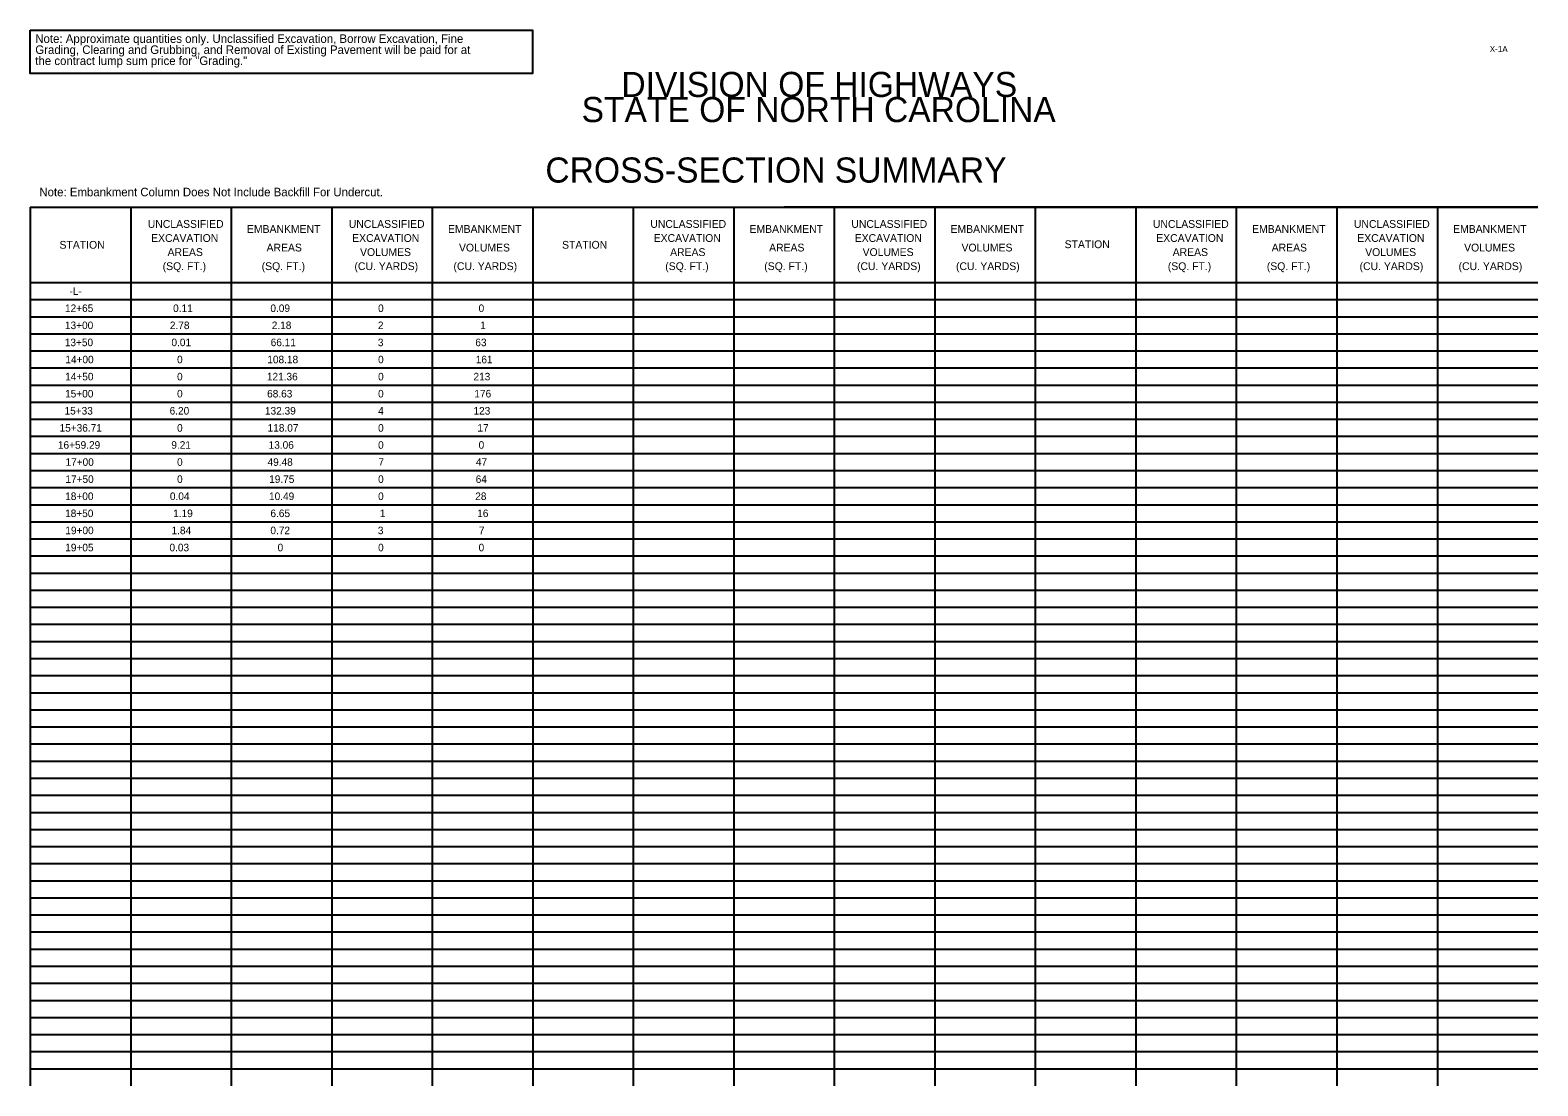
# Model space of a CAD drawing. Extents: x 2473106 to 2475402, y 633617 to 633851.
# Drawn here: x 2473105.7 to 2473405.7, y 633617.5 to 633827.5 of the extents above; entities that cross this region are included whole.
import ezdxf

# ---------------------------------------------------------------- set-up
doc = ezdxf.new("R2010")
doc.units = 0
for name, color, linetype in [('Prop CMT Shld Paved Course 2', 7, 'Continuous'), ('Prop CMT Subgrade Earthwork', 7, 'Continuous'), ('Prop XS SE Text', 7, 'Continuous')]:
    doc.layers.add(name, color=color, linetype=linetype)

msp = doc.modelspace()

# ---------------------------------------------------------------- linework, layer by layer
at = {"layer": 'Prop CMT Subgrade Earthwork'}
msp.add_lwpolyline([(2473105.69, 633827.47), (2473205.67, 633827.47), (2473205.67, 633818.82), (2473105.69, 633818.82)], close=True, dxfattribs=at)
at = {"layer": 'Prop XS SE Text'}
for p, q in [((2473105.69, 633792.27), (2473405.69, 633792.37)), ((2473105.69, 633792.27), (2473405.69, 633792.27)), ((2473105.69, 633792.27), (2473105.69, 633617.47)), ((2473125.69, 633792.27), (2473125.69, 633617.47)), ((2473145.69, 633792.27), (2473145.69, 633617.47)), ((2473165.69, 633792.27), (2473165.69, 633617.47)), ((2473185.69, 633792.27), (2473185.69, 633617.47)), ((2473205.69, 633792.27), (2473205.69, 633617.47)), ((2473225.69, 633792.27), (2473225.69, 633617.47)), ((2473245.69, 633792.27), (2473245.69, 633617.47)), ((2473265.69, 633792.27), (2473265.69, 633617.47)), ((2473285.69, 633792.27), (2473285.69, 633617.47)), ((2473305.69, 633792.27), (2473305.69, 633617.47)), ((2473325.69, 633792.27), (2473325.69, 633617.47)), ((2473345.69, 633792.27), (2473345.69, 633617.47)), ((2473365.69, 633792.27), (2473365.69, 633617.47)), ((2473385.69, 633792.27), (2473385.69, 633617.47)), ((2473105.69, 633777.27), (2473405.69, 633777.27)), ((2473105.69, 633773.87), (2473405.69, 633773.87)), ((2473105.69, 633770.47), (2473405.69, 633770.47)), ((2473105.69, 633767.07), (2473405.69, 633767.07)), ((2473105.69, 633763.67), (2473405.69, 633763.67)), ((2473105.69, 633760.27), (2473405.69, 633760.27)), ((2473105.69, 633756.87), (2473405.69, 633756.87)), ((2473105.69, 633753.47), (2473405.69, 633753.47)), ((2473105.69, 633750.07), (2473405.69, 633750.07)), ((2473105.69, 633746.67), (2473405.69, 633746.67)), ((2473105.69, 633743.27), (2473405.69, 633743.27)), ((2473105.69, 633739.87), (2473405.69, 633739.87)), ((2473105.69, 633736.47), (2473405.69, 633736.47)), ((2473105.69, 633736.47), (2473405.69, 633736.47)), ((2473105.69, 633733.07), (2473405.69, 633733.07)), ((2473105.69, 633729.67), (2473405.69, 633729.67)), ((2473105.69, 633726.27), (2473405.69, 633726.27)), ((2473105.69, 633722.87), (2473405.69, 633722.87)), ((2473105.69, 633719.47), (2473405.69, 633719.47)), ((2473105.69, 633716.07), (2473405.69, 633716.07)), ((2473105.69, 633712.67), (2473405.69, 633712.67)), ((2473105.69, 633709.27), (2473405.69, 633709.27)), ((2473105.69, 633705.87), (2473405.69, 633705.87)), ((2473105.69, 633702.47), (2473405.69, 633702.47)), ((2473105.69, 633699.07), (2473405.69, 633699.07)), ((2473105.69, 633695.67), (2473405.69, 633695.67)), ((2473105.69, 633692.27), (2473405.69, 633692.27)), ((2473105.69, 633688.87), (2473405.69, 633688.87)), ((2473105.69, 633685.47), (2473405.69, 633685.47)), ((2473105.69, 633682.07), (2473405.69, 633682.07)), ((2473105.69, 633678.67), (2473405.69, 633678.67)), ((2473105.69, 633675.27), (2473405.69, 633675.27)), ((2473105.69, 633671.87), (2473405.69, 633671.87)), ((2473105.69, 633668.47), (2473405.69, 633668.47)), ((2473105.69, 633665.07), (2473405.69, 633665.07)), ((2473105.69, 633661.67), (2473405.69, 633661.67)), ((2473105.69, 633658.27), (2473405.69, 633658.27)), ((2473105.69, 633654.87), (2473405.69, 633654.87)), ((2473105.69, 633651.47), (2473405.69, 633651.47)), ((2473105.69, 633648.07), (2473405.69, 633648.07)), ((2473105.69, 633644.67), (2473405.69, 633644.67)), ((2473105.69, 633641.27), (2473405.69, 633641.27)), ((2473105.69, 633637.87), (2473405.69, 633637.87)), ((2473105.69, 633634.47), (2473405.69, 633634.47)), ((2473105.69, 633631.07), (2473405.69, 633631.07)), ((2473105.69, 633627.67), (2473405.69, 633627.67)), ((2473105.69, 633624.27), (2473405.69, 633624.27)), ((2473105.69, 633620.87), (2473405.69, 633620.87))]:
    msp.add_line(p, q, dxfattribs=at)

# ---------------------------------------------------------------- texts
at = {"layer": 'Prop CMT Shld Paved Course 2'}
for s, p in [('Note: Approximate quantities only. Unclassified Excavation, Borrow Excavation, Fine ', (2473106.71, 633824.93)), ('the contract lump sum price for "Grading."', (2473106.71, 633820.53)), ('Grading, Clearing and Grubbing, and Removal of Existing Pavement will be paid for at', (2473106.71, 633822.73))]:
    msp.add_text(s, height=1.7, dxfattribs=at).set_placement(p)
msp.add_text('Note: Embankment Column Does Not Include Backfill For Undercut.', height=1.7, rotation=360, dxfattribs=at).set_placement((2473107.52, 633794.42))
at = {"layer": 'Prop XS SE Text'}
for s, height, p in [('X-1A', 1.2, (2473396.12, 633823.11)), ('CROSS-SECTION SUMMARY', 5, (2473208.21, 633797.14)), ('UNCLASSIFIED', 1.55, (2473129.09, 633788.14)), ('UNCLASSIFIED', 1.55, (2473169.09, 633788.14)), ('UNCLASSIFIED', 1.55, (2473229.09, 633788.14)), ('UNCLASSIFIED', 1.55, (2473269.09, 633788.14)), ('UNCLASSIFIED', 1.55, (2473329.09, 633788.14)), ('UNCLASSIFIED', 1.55, (2473369.09, 633788.14)), ('EXCAVATION', 1.55, (2473129.76, 633785.34)), ('EMBANKMENT', 1.55, (2473148.83, 633787.14)), ('EXCAVATION', 1.55, (2473169.76, 633785.34)), ('EMBANKMENT', 1.55, (2473188.83, 633787.14)), ('EXCAVATION', 1.55, (2473229.76, 633785.34)), ('EMBANKMENT', 1.55, (2473248.83, 633787.14)), ('EXCAVATION', 1.55, (2473269.76, 633785.34)), ('EMBANKMENT', 1.55, (2473288.83, 633787.14)), ('EXCAVATION', 1.55, (2473329.76, 633785.34)), ('EMBANKMENT', 1.55, (2473348.83, 633787.14)), ('EXCAVATION', 1.55, (2473369.76, 633785.34)), ('EMBANKMENT', 1.55, (2473388.83, 633787.14)), ('STATION', 1.55, (2473111.53, 633783.99)), ('AREAS', 1.55, (2473133.03, 633782.54)), ('AREAS', 1.55, (2473152.73, 633783.44)), ('VOLUMES', 1.55, (2473171.33, 633782.54)), ('VOLUMES', 1.55, (2473191.02, 633783.44)), ('STATION', 1.55, (2473211.53, 633783.99)), ('AREAS', 1.55, (2473233.03, 633782.54)), ('AREAS', 1.55, (2473252.73, 633783.44)), ('VOLUMES', 1.55, (2473271.33, 633782.54)), ('VOLUMES', 1.55, (2473291.02, 633783.44)), ('STATION', 1.55, (2473311.53, 633784.1)), ('AREAS', 1.55, (2473333.03, 633782.54)), ('AREAS', 1.55, (2473352.73, 633783.44)), ('VOLUMES', 1.55, (2473371.33, 633782.54)), ('VOLUMES', 1.55, (2473391.02, 633783.44)), ('(SQ. FT.)', 1.55, (2473132.06, 633779.74)), ('(SQ. FT.)', 1.55, (2473151.76, 633779.74)), ('(CU. YARDS)', 1.55, (2473170.22, 633779.74)), ('(CU. YARDS)', 1.55, (2473189.92, 633779.74)), ('(SQ. FT.)', 1.55, (2473232.06, 633779.74)), ('(SQ. FT.)', 1.55, (2473251.76, 633779.74)), ('(CU. YARDS)', 1.55, (2473270.22, 633779.74)), ('(CU. YARDS)', 1.55, (2473289.92, 633779.74)), ('(SQ. FT.)', 1.55, (2473332.06, 633779.74)), ('(SQ. FT.)', 1.55, (2473351.76, 633779.74)), ('(CU. YARDS)', 1.55, (2473370.22, 633779.74)), ('(CU. YARDS)', 1.55, (2473389.92, 633779.74)), ('-L-', 1.5, (2473113.5, 633774.8)), ('12+65', 1.5, (2473112.62, 633771.4)), ('0.11', 1.5, (2473134.13, 633771.4)), ('0.09', 1.5, (2473153.49, 633771.4)), ('0', 1.5, (2473174.92, 633771.4)), ('0', 1.5, (2473194.92, 633771.4)), ('13+00', 1.5, (2473112.61, 633768)), ('2.78', 1.5, (2473133.49, 633768)), ('2.18', 1.5, (2473153.76, 633768)), ('2', 1.5, (2473174.88, 633768)), ('1', 1.5, (2473195.25, 633768)), ('13+50', 1.5, (2473112.58, 633764.6)), ('0.01', 1.5, (2473133.8, 633764.6)), ('66.11', 1.5, (2473153.55, 633764.6)), ('3', 1.5, (2473174.87, 633764.6)), ('63', 1.5, (2473194.27, 633764.6)), ('14+00', 1.5, (2473112.69, 633761.2)), ('0', 1.5, (2473134.92, 633761.2)), ('108.18', 1.5, (2473152.88, 633761.2)), ('0', 1.5, (2473174.92, 633761.2)), ('161', 1.5, (2473194.35, 633761.2)), ('14+50', 1.5, (2473112.66, 633757.8)), ('0', 1.5, (2473134.92, 633757.8)), ('121.36', 1.5, (2473152.79, 633757.8)), ('0', 1.5, (2473174.92, 633757.8)), ('213', 1.5, (2473193.9, 633757.8)), ('15+00', 1.5, (2473112.64, 633754.4)), ('0', 1.5, (2473134.92, 633754.4)), ('68.63', 1.5, (2473152.84, 633754.4)), ('0', 1.5, (2473174.92, 633754.4)), ('176', 1.5, (2473194.08, 633754.4)), ('15+33', 1.5, (2473112.53, 633751)), ('6.20', 1.5, (2473133.44, 633751)), ('132.39', 1.5, (2473152.41, 633751)), ('4', 1.5, (2473174.94, 633751)), ('123', 1.5, (2473193.9, 633751)), ('15+36.71', 1.5, (2473111.54, 633747.6)), ('0', 1.5, (2473134.92, 633747.6)), ('118.07', 1.5, (2473152.94, 633747.6)), ('0', 1.5, (2473174.92, 633747.6)), ('17', 1.5, (2473194.68, 633747.6)), ('16+59.29', 1.5, (2473111.21, 633744.2)), ('9.21', 1.5, (2473133.78, 633744.2)), ('13.06', 1.5, (2473153.14, 633744.2)), ('0', 1.5, (2473174.92, 633744.2)), ('0', 1.5, (2473194.92, 633744.2)), ('17+00', 1.5, (2473112.72, 633740.8)), ('0', 1.5, (2473134.92, 633740.8)), ('49.48', 1.5, (2473152.92, 633740.8)), ('7', 1.5, (2473174.98, 633740.8)), ('47', 1.5, (2473194.38, 633740.8)), ('17+50', 1.5, (2473112.7, 633737.4)), ('0', 1.5, (2473134.92, 633737.4)), ('19.75', 1.5, (2473153.24, 633737.4)), ('0', 1.5, (2473174.92, 633737.4)), ('64', 1.5, (2473194.34, 633737.4)), ('18+00', 1.5, (2473112.66, 633734)), ('0.04', 1.5, (2473133.49, 633734)), ('10.49', 1.5, (2473153.22, 633734)), ('0', 1.5, (2473174.92, 633734)), ('28', 1.5, (2473194.25, 633734)), ('18+50', 1.5, (2473112.64, 633730.6)), ('1.19', 1.5, (2473134.15, 633730.6)), ('6.65', 1.5, (2473153.5, 633730.6)), ('1', 1.5, (2473175.25, 633730.6)), ('16', 1.5, (2473194.65, 633730.6)), ('19+00', 1.5, (2473112.69, 633727.2)), ('1.84', 1.5, (2473133.82, 633727.2)), ('0.72', 1.5, (2473153.49, 633727.2)), ('3', 1.5, (2473174.87, 633727.2)), ('7', 1.5, (2473194.98, 633727.2)), ('19+05', 1.5, (2473112.67, 633723.8)), ('0.03', 1.5, (2473133.41, 633723.8)), ('0', 1.5, (2473154.92, 633723.8)), ('0', 1.5, (2473174.92, 633723.8)), ('0', 1.5, (2473194.92, 633723.8))]:
    msp.add_text(s, height=height, dxfattribs=at).set_placement(p)
for s, p in [('DIVISION OF HIGHWAYS', (2473223.33, 633814.17)), ('STATE OF NORTH CAROLINA', (2473215.41, 633809.17))]:
    msp.add_text(s, height=4.9999, rotation=360, dxfattribs=at).set_placement(p)

doc.saveas('drawing.dxf')
